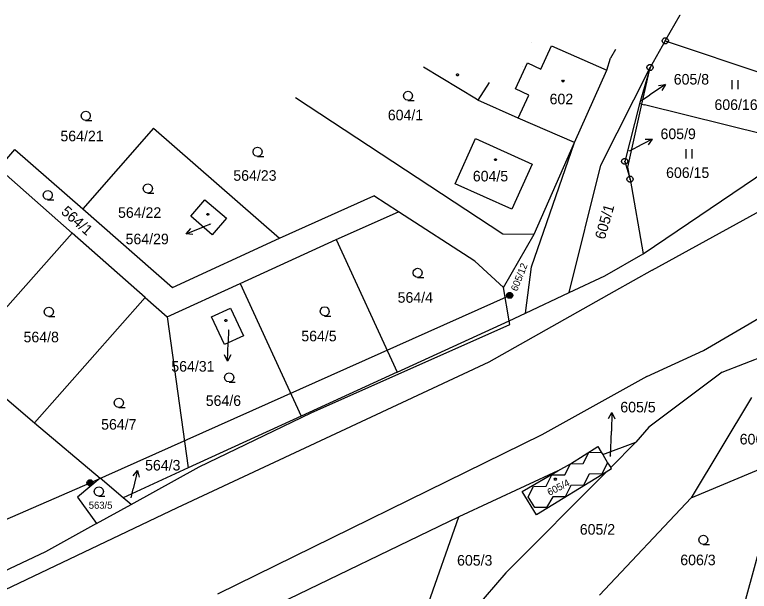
# Model space of a CAD drawing. Extents: x -759699 to -757730, y -1172308 to -1170857.
# Drawn here: x -759051 to -758932.7, y -1171592 to -1171499.1 of the extents above; entities that cross this region are included whole.
import ezdxf

# ---------------------------------------------------------------- set-up
doc = ezdxf.new("R2010")
doc.units = 0
for name, color, linetype in [('Vrstva 1', 7, 'Continuous'), ('Vrstva 12', 7, 'Continuous'), ('Vrstva 2', 7, 'Continuous'), ('Vrstva 3', 7, 'Continuous'), ('Vrstva 4', 7, 'Continuous'), ('Vrstva 5', 7, 'Continuous'), ('Vrstva 6', 7, 'Continuous'), ('Vrstva 7', 7, 'Continuous'), ('Vrstva 8', 7, 'Continuous')]:
    doc.layers.add(name, color=color, linetype=linetype)

msp = doc.modelspace()

# ---------------------------------------------------------------- linework, layer by layer
at = {"layer": 'Vrstva 1'}
for p, q in [((-758946.27, -1171503.31), (-758943.88, -1171499.09)), ((-758943.88, -1171499.09), (-758943.88, -1171499.09)), ((-758946.27, -1171503.31), (-758948.7, -1171507.6)), ((-758946.27, -1171503.31), (-758914.82, -1171513.88)), ((-758967.79, -1171503.49), (-758967.79, -1171503.49)), ((-758967.79, -1171503.49), (-758967.79, -1171503.49)), ((-758954.28, -1171504.71), (-758955.09, -1171506.07)), ((-758954.28, -1171504.71), (-758954.28, -1171504.71)), ((-758954.28, -1171504.71), (-758954.28, -1171504.71)), ((-758955.66, -1171508.01), (-758955.09, -1171506.07)), ((-758955.09, -1171506.07), (-758955.09, -1171506.07)), ((-758976.64, -1171512.71), (-758985.21, -1171507.56)), ((-758985.21, -1171507.56), (-758985.21, -1171507.56)), ((-758969.29, -1171507.45), (-758969.29, -1171507.45)), ((-758969.29, -1171507.45), (-758969.29, -1171507.45)), ((-758960.9, -1171519.69), (-758955.66, -1171508.01)), ((-758956.62, -1171523.33), (-758948.7, -1171507.6)), ((-758948.7, -1171507.6), (-758950.4, -1171513.43)), ((-758950.02, -1171513.52), (-758948.7, -1171507.6)), ((-759005.8, -1171512.44), (-759005.8, -1171512.44)), ((-759005.8, -1171512.44), (-759005.8, -1171512.44)), ((-759005.8, -1171512.44), (-758972.4, -1171534.4)), ((-758976.44, -1171512.83), (-758976.64, -1171512.71)), ((-758969.95, -1171515.76), (-758976.44, -1171512.83)), ((-758950.4, -1171513.43), (-758952.79, -1171522.73)), ((-758952.28, -1171523.63), (-758950.02, -1171513.52)), ((-758950.02, -1171513.52), (-758950.4, -1171513.43)), ((-758950.02, -1171513.52), (-758949.6, -1171513.62)), ((-758923.84, -1171519.99), (-758949.6, -1171513.62)), ((-758960.9, -1171519.69), (-758969.95, -1171515.76)), ((-759028.64, -1171517.34), (-759040.04, -1171530.35)), ((-759028.64, -1171517.34), (-759028.64, -1171517.34)), ((-759028.64, -1171517.34), (-759008.36, -1171535.09)), ((-758980.08, -1171526.33), (-758976.79, -1171519.04)), ((-758976.79, -1171519.04), (-758967.68, -1171523.15)), ((-758967.79, -1171539.68), (-758960.9, -1171519.69)), ((-758967.38, -1171534.45), (-758960.9, -1171519.69)), ((-759052.28, -1171522.29), (-759050.96, -1171520.79)), ((-759050.96, -1171520.79), (-759050.96, -1171520.79)), ((-759050.96, -1171520.79), (-759040.04, -1171530.35)), ((-758949.81, -1171537.59), (-758925.08, -1171520.83)), ((-758967.68, -1171523.15), (-758970.97, -1171530.42)), ((-758961.73, -1171543.84), (-758956.62, -1171523.33)), ((-758952.79, -1171522.73), (-758951.93, -1171525.59)), ((-759041.76, -1171534.25), (-759052.86, -1171524.45)), ((-758951.93, -1171525.59), (-758952.28, -1171523.63)), ((-758951.93, -1171525.59), (-758949.81, -1171537.59)), ((-758970.97, -1171530.42), (-758980.08, -1171526.33)), ((-759022.64, -1171531.54), (-759020.38, -1171528.89)), ((-759020.38, -1171528.89), (-759016.91, -1171531.88)), ((-759008.36, -1171535.09), (-758993.17, -1171528.25)), ((-758993.17, -1171528.25), (-758993.17, -1171528.25)), ((-758989.2, -1171530.82), (-758993.17, -1171528.25)), ((-759040.04, -1171530.35), (-759025.59, -1171543)), ((-759019.22, -1171534.55), (-759022.64, -1171531.54)), ((-758999.24, -1171535.3), (-758989.2, -1171530.82)), ((-758976.9, -1171538.8), (-758989.2, -1171530.82)), ((-759016.91, -1171531.88), (-759019.22, -1171534.55)), ((-759059.77, -1171554.66), (-759041.76, -1171534.25)), ((-759029.99, -1171544.64), (-759041.76, -1171534.25)), ((-759025.59, -1171543), (-759008.36, -1171535.09)), ((-759014.69, -1171542.38), (-758999.24, -1171535.3)), ((-758999.24, -1171535.3), (-758989.44, -1171556.65)), ((-758972.4, -1171534.4), (-758967.38, -1171534.45)), ((-758972.3, -1171543), (-758967.38, -1171534.45)), ((-758955.97, -1171541.14), (-758949.81, -1171537.59)), ((-758972.3, -1171543), (-758976.9, -1171538.8)), ((-758968.78, -1171547.15), (-758967.79, -1171539.68)), ((-758961.73, -1171543.84), (-758955.97, -1171541.14)), ((-759026.44, -1171547.77), (-759014.69, -1171542.38)), ((-759014.69, -1171542.38), (-759004.89, -1171563.74)), ((-758971.4, -1171548.38), (-758972.3, -1171543)), ((-759047.8, -1171564.8), (-759029.99, -1171544.64)), ((-759029.99, -1171544.64), (-759026.44, -1171547.77)), ((-758968.78, -1171547.15), (-758961.73, -1171543.84)), ((-759019.34, -1171547.74), (-759016.26, -1171546.38)), ((-759016.26, -1171546.38), (-759014.14, -1171550.81)), ((-759026.44, -1171547.77), (-759023.07, -1171572.08)), ((-759017.21, -1171552.22), (-759019.34, -1171547.74)), ((-758971.4, -1171548.38), (-758968.78, -1171547.15)), ((-759003.26, -1171563.2), (-758971.3, -1171549)), ((-758989.44, -1171556.65), (-758971.4, -1171548.38)), ((-758971.3, -1171549), (-758971.4, -1171548.38)), ((-758937.1, -1171556.66), (-758918.53, -1171549.43)), ((-759014.14, -1171550.81), (-759017.21, -1171552.22)), ((-759059.77, -1171554.66), (-759047.8, -1171564.8)), ((-758989.44, -1171556.65), (-759004.89, -1171563.74)), ((-758937.1, -1171556.66), (-758948.93, -1171565.54)), ((-758932.37, -1171560.76), (-758942.1, -1171576.91)), ((-759021.28, -1171571.93), (-759003.26, -1171563.2)), ((-759047.8, -1171564.8), (-759037.25, -1171573.72)), ((-759004.89, -1171563.74), (-759023.07, -1171572.08)), ((-758948.93, -1171565.54), (-758950.99, -1171567.95)), ((-758956.34, -1171569.92), (-758950.99, -1171567.95)), ((-758950.99, -1171567.95), (-758955.05, -1171572.03)), ((-758961.54, -1171571.4), (-758957.13, -1171568.64)), ((-758957.13, -1171568.64), (-758956.6, -1171569.57)), ((-758956.6, -1171569.57), (-758956.34, -1171569.92)), ((-758956.34, -1171569.92), (-758955.56, -1171571.28)), ((-758942.1, -1171576.91), (-758927.21, -1171570.62)), ((-758927.21, -1171570.62), (-758933.5, -1171593.84)), ((-759032.25, -1171578), (-759021.28, -1171571.93)), ((-758963.54, -1171572.57), (-758961.54, -1171571.4)), ((-758955.56, -1171571.28), (-758955.05, -1171572.03)), ((-759023.07, -1171572.08), (-759033.52, -1171576.88)), ((-758963.54, -1171572.57), (-758979.51, -1171579.97)), ((-758971.93, -1171588.99), (-758955.78, -1171572.76)), ((-758969.29, -1171575.88), (-758963.54, -1171572.57)), ((-758955.78, -1171572.76), (-758966.97, -1171579.63)), ((-758954.92, -1171572.23), (-758955.78, -1171572.76)), ((-758954.92, -1171572.23), (-758955.05, -1171572.03)), ((-759037.25, -1171573.72), (-759040.91, -1171576.77)), ((-759033.52, -1171576.88), (-759037.25, -1171573.72)), ((-758966.97, -1171579.63), (-758969.29, -1171575.88)), ((-759040.91, -1171576.77), (-759037.82, -1171581.06)), ((-759032.25, -1171578), (-759033.52, -1171576.88)), ((-758956.83, -1171592.6), (-758942.1, -1171576.91)), ((-759037.82, -1171581.06), (-759032.25, -1171578)), ((-758979.51, -1171579.97), (-759011.7, -1171595.5)), ((-758985.06, -1171595.81), (-758979.51, -1171579.97)), ((-759037.82, -1171581.06), (-759046.04, -1171585.58)), ((-759046.04, -1171585.58), (-759059.5, -1171591.95)), ((-758971.93, -1171588.99), (-758979.59, -1171597.85))]:
    msp.add_line(p, q, dxfattribs=at)
at = {"layer": 'Vrstva 12'}
for p, q in [((-758967.79, -1171503.49), (-758967.79, -1171503.49)), ((-758967.79, -1171503.49), (-758967.79, -1171503.49)), ((-758966.3, -1171507.85), (-758964.58, -1171504.08)), ((-758964.58, -1171504.08), (-758955.66, -1171508.01)), ((-758970.39, -1171511.05), (-758968.46, -1171506.86)), ((-758968.46, -1171506.86), (-758966.3, -1171507.85)), ((-758960.9, -1171519.69), (-758955.66, -1171508.01)), ((-758968.23, -1171512.04), (-758970.39, -1171511.05)), ((-758969.95, -1171515.76), (-758968.23, -1171512.04)), ((-758960.9, -1171519.69), (-758969.95, -1171515.76)), ((-758980.08, -1171526.33), (-758976.79, -1171519.04)), ((-758976.79, -1171519.04), (-758967.68, -1171523.15)), ((-758967.68, -1171523.15), (-758970.97, -1171530.42)), ((-758970.97, -1171530.42), (-758980.08, -1171526.33)), ((-759022.64, -1171531.54), (-759020.38, -1171528.89)), ((-759020.38, -1171528.89), (-759016.91, -1171531.88)), ((-759019.22, -1171534.55), (-759022.64, -1171531.54)), ((-759016.91, -1171531.88), (-759019.22, -1171534.55)), ((-759019.34, -1171547.74), (-759016.26, -1171546.38)), ((-759016.26, -1171546.38), (-759014.14, -1171550.81)), ((-759017.21, -1171552.22), (-759019.34, -1171547.74)), ((-759014.14, -1171550.81), (-759017.21, -1171552.22)), ((-758959.48, -1171571.37), (-758958.55, -1171569.6)), ((-758958.55, -1171569.6), (-758956.6, -1171569.57)), ((-758956.6, -1171569.57), (-758956.34, -1171569.92)), ((-758956.34, -1171569.92), (-758955.56, -1171571.28)), ((-758962.44, -1171573.17), (-758961.54, -1171571.4)), ((-758961.54, -1171571.4), (-758959.48, -1171571.37)), ((-758955.56, -1171571.28), (-758956.49, -1171573.05)), ((-758958.5, -1171573.08), (-758959.43, -1171574.85)), ((-758956.49, -1171573.05), (-758958.5, -1171573.08)), ((-758965.46, -1171575.01), (-758964.51, -1171573.22)), ((-758964.51, -1171573.22), (-758962.44, -1171573.17)), ((-758968.33, -1171576.75), (-758967.46, -1171575.07)), ((-758967.46, -1171575.07), (-758965.46, -1171575.01)), ((-758961.46, -1171574.91), (-758962.39, -1171576.72)), ((-758959.43, -1171574.85), (-758961.46, -1171574.91)), ((-758967.26, -1171578.47), (-758968.33, -1171576.75)), ((-758964.38, -1171576.73), (-758965.36, -1171578.48)), ((-758962.39, -1171576.72), (-758964.38, -1171576.73)), ((-758965.36, -1171578.48), (-758967.26, -1171578.47))]:
    msp.add_line(p, q, dxfattribs=at)
at = {"layer": 'Vrstva 3'}
for p, q in [((-758935.54, -1171509.61), (-758935.54, -1171511.11)), ((-758934.54, -1171511.11), (-758934.54, -1171509.61)), ((-758942.95, -1171520.75), (-758942.95, -1171522.25)), ((-758941.95, -1171522.25), (-758941.95, -1171520.75))]:
    msp.add_line(p, q, dxfattribs=at)
for points in [[(-758987.67, -1171512.88), (-758988.05, -1171512.78), (-758988.32, -1171512.51), (-758988.42, -1171512.14), (-758988.32, -1171511.77), (-758988.05, -1171511.5), (-758987.68, -1171511.4), (-758987.31, -1171511.5), (-758987.04, -1171511.77), (-758986.94, -1171512.15), (-758987.04, -1171512.53), (-758987.31, -1171512.8), (-758987.69, -1171512.9), (-758986.69, -1171512.9)], [(-759039.55, -1171516.12), (-759039.93, -1171516.02), (-759040.2, -1171515.75), (-759040.3, -1171515.38), (-759040.2, -1171515.01), (-759039.93, -1171514.74), (-759039.56, -1171514.64), (-759039.19, -1171514.74), (-759038.92, -1171515.01), (-759038.82, -1171515.39), (-759038.92, -1171515.77), (-759039.19, -1171516.04), (-759039.57, -1171516.14), (-759038.57, -1171516.14)], [(-759011.88, -1171521.92), (-759012.26, -1171521.82), (-759012.53, -1171521.55), (-759012.63, -1171521.18), (-759012.53, -1171520.81), (-759012.26, -1171520.54), (-759011.89, -1171520.44), (-759011.52, -1171520.54), (-759011.25, -1171520.81), (-759011.15, -1171521.19), (-759011.25, -1171521.57), (-759011.52, -1171521.84), (-759011.9, -1171521.94), (-759010.9, -1171521.94)], [(-759029.55, -1171527.81), (-759029.93, -1171527.71), (-759030.2, -1171527.44), (-759030.3, -1171527.07), (-759030.2, -1171526.7), (-759029.93, -1171526.43), (-759029.56, -1171526.33), (-759029.19, -1171526.43), (-759028.92, -1171526.7), (-759028.82, -1171527.08), (-759028.92, -1171527.46), (-759029.19, -1171527.73), (-759029.57, -1171527.83), (-759028.57, -1171527.83)], [(-759045.67, -1171528.88), (-759046.05, -1171528.78), (-759046.32, -1171528.51), (-759046.42, -1171528.14), (-759046.32, -1171527.77), (-759046.05, -1171527.5), (-759045.68, -1171527.4), (-759045.31, -1171527.5), (-759045.04, -1171527.77), (-759044.94, -1171528.15), (-759045.04, -1171528.53), (-759045.31, -1171528.8), (-759045.69, -1171528.9), (-759044.69, -1171528.9)], [(-758986.12, -1171541.39), (-758986.5, -1171541.29), (-758986.77, -1171541.02), (-758986.87, -1171540.65), (-758986.77, -1171540.28), (-758986.5, -1171540.01), (-758986.13, -1171539.91), (-758985.76, -1171540.01), (-758985.49, -1171540.28), (-758985.39, -1171540.66), (-758985.49, -1171541.04), (-758985.76, -1171541.31), (-758986.14, -1171541.41), (-758985.14, -1171541.41)], [(-759045.5, -1171547.69), (-759045.88, -1171547.59), (-759046.15, -1171547.32), (-759046.25, -1171546.95), (-759046.15, -1171546.58), (-759045.88, -1171546.31), (-759045.51, -1171546.21), (-759045.14, -1171546.31), (-759044.87, -1171546.58), (-759044.77, -1171546.96), (-759044.87, -1171547.34), (-759045.14, -1171547.61), (-759045.52, -1171547.71), (-759044.52, -1171547.71)], [(-759001.09, -1171547.6), (-759001.47, -1171547.5), (-759001.74, -1171547.23), (-759001.84, -1171546.86), (-759001.74, -1171546.49), (-759001.47, -1171546.22), (-759001.1, -1171546.12), (-759000.73, -1171546.22), (-759000.46, -1171546.49), (-759000.36, -1171546.87), (-759000.46, -1171547.25), (-759000.73, -1171547.52), (-759001.11, -1171547.62), (-759000.11, -1171547.62)], [(-759016.46, -1171558.24), (-759016.84, -1171558.14), (-759017.11, -1171557.87), (-759017.21, -1171557.5), (-759017.11, -1171557.13), (-759016.84, -1171556.86), (-759016.47, -1171556.76), (-759016.1, -1171556.86), (-759015.83, -1171557.13), (-759015.73, -1171557.51), (-759015.83, -1171557.89), (-759016.1, -1171558.16), (-759016.48, -1171558.26), (-759015.48, -1171558.26)], [(-759034.21, -1171562.33), (-759034.59, -1171562.23), (-759034.86, -1171561.96), (-759034.96, -1171561.59), (-759034.86, -1171561.22), (-759034.59, -1171560.95), (-759034.22, -1171560.85), (-759033.85, -1171560.95), (-759033.58, -1171561.22), (-759033.48, -1171561.6), (-759033.58, -1171561.98), (-759033.85, -1171562.25), (-759034.23, -1171562.35), (-759033.23, -1171562.35)], [(-759037.45, -1171576.61), (-759037.83, -1171576.51), (-759038.1, -1171576.24), (-759038.2, -1171575.87), (-759038.1, -1171575.5), (-759037.83, -1171575.23), (-759037.46, -1171575.13), (-759037.09, -1171575.23), (-759036.82, -1171575.5), (-759036.72, -1171575.88), (-759036.82, -1171576.26), (-759037.09, -1171576.53), (-759037.47, -1171576.63), (-759036.47, -1171576.63)], [(-758940.13, -1171584.39), (-758940.51, -1171584.29), (-758940.78, -1171584.02), (-758940.88, -1171583.65), (-758940.78, -1171583.28), (-758940.51, -1171583.01), (-758940.14, -1171582.91), (-758939.77, -1171583.01), (-758939.5, -1171583.28), (-758939.4, -1171583.66), (-758939.5, -1171584.04), (-758939.77, -1171584.31), (-758940.15, -1171584.41), (-758939.15, -1171584.41)]]:
    msp.add_lwpolyline(points, dxfattribs=at)
at = {"layer": 'Vrstva 4'}
for p, q in [((-758966.3, -1171507.85), (-758964.58, -1171504.08)), ((-758964.58, -1171504.08), (-758955.66, -1171508.01)), ((-758970.39, -1171511.05), (-758968.46, -1171506.86)), ((-758968.46, -1171506.86), (-758966.3, -1171507.85)), ((-758985.21, -1171507.56), (-758985.21, -1171507.56)), ((-758974.59, -1171510), (-758976.44, -1171512.83)), ((-758974.59, -1171510), (-758974.59, -1171510)), ((-758968.23, -1171512.04), (-758970.39, -1171511.05)), ((-758969.95, -1171515.76), (-758968.23, -1171512.04)), ((-758948.39, -1171540.22), (-758926.31, -1171528.12)), ((-758940.14, -1171553.19), (-758911.34, -1171536.26)), ((-758948.39, -1171540.22), (-758954.49, -1171543.68)), ((-758954.49, -1171543.68), (-758974.67, -1171555.07)), ((-758949.21, -1171557.34), (-758940.14, -1171553.19)), ((-758974.67, -1171555.07), (-759024.83, -1171578.53)), ((-758949.21, -1171557.34), (-758966.16, -1171566.77)), ((-758966.16, -1171566.77), (-759018.34, -1171592.41)), ((-758959.48, -1171571.37), (-758958.55, -1171569.6)), ((-758958.55, -1171569.6), (-758956.6, -1171569.57)), ((-758962.44, -1171573.17), (-758961.54, -1171571.4)), ((-758961.54, -1171571.4), (-758959.48, -1171571.37)), ((-758955.56, -1171571.28), (-758956.49, -1171573.05)), ((-758958.5, -1171573.08), (-758959.43, -1171574.85)), ((-758956.49, -1171573.05), (-758958.5, -1171573.08)), ((-758965.46, -1171575.01), (-758964.51, -1171573.22)), ((-758964.51, -1171573.22), (-758962.44, -1171573.17)), ((-758968.33, -1171576.75), (-758967.46, -1171575.07)), ((-758967.46, -1171575.07), (-758965.46, -1171575.01)), ((-758961.46, -1171574.91), (-758962.39, -1171576.72)), ((-758959.43, -1171574.85), (-758961.46, -1171574.91)), ((-758967.26, -1171578.47), (-758968.33, -1171576.75)), ((-758964.38, -1171576.73), (-758965.36, -1171578.48)), ((-758962.39, -1171576.72), (-758964.38, -1171576.73)), ((-759024.83, -1171578.53), (-759072.45, -1171601.16)), ((-758965.36, -1171578.48), (-758967.26, -1171578.47))]:
    msp.add_line(p, q, dxfattribs=at)
at = {"layer": 'Vrstva 5'}
for points in [[(-758979.62, -1171508.62), (-758979.53, -1171508.77), (-758979.62, -1171508.92), (-758979.8, -1171508.92), (-758979.89, -1171508.77), (-758979.8, -1171508.62)], [(-758962.64, -1171509.63), (-758962.55, -1171509.78), (-758962.64, -1171509.93), (-758962.82, -1171509.93), (-758962.91, -1171509.78), (-758962.82, -1171509.63)], [(-758973.51, -1171522.28), (-758973.42, -1171522.43), (-758973.51, -1171522.58), (-758973.69, -1171522.58), (-758973.78, -1171522.43), (-758973.69, -1171522.28)], [(-759019.81, -1171531.1), (-759019.72, -1171531.25), (-759019.81, -1171531.4), (-759019.99, -1171531.4), (-759020.08, -1171531.25), (-759019.99, -1171531.1)], [(-759016.91, -1171548.19), (-759016.82, -1171548.34), (-759016.91, -1171548.49), (-759017.09, -1171548.49), (-759017.18, -1171548.34), (-759017.09, -1171548.19)], [(-758963.86, -1171573.75), (-758963.77, -1171573.9), (-758963.86, -1171574.05), (-758964.04, -1171574.05), (-758964.13, -1171573.9), (-758964.04, -1171573.75)]]:
    msp.add_lwpolyline(points, close=True, dxfattribs=at)
at = {"layer": 'Vrstva 6'}
for p, q in [((-759038.87, -1171574.49), (-758971.32, -1171544.31)), ((-759105.39, -1171603.36), (-759038.87, -1171574.49))]:
    msp.add_line(p, q, dxfattribs=at)
for points in [[(-758971.47, -1171543.83), (-758971.16, -1171543.83), (-758970.91, -1171544.01), (-758970.81, -1171544.3), (-758970.91, -1171544.59), (-758971.16, -1171544.77), (-758971.47, -1171544.77), (-758971.72, -1171544.59), (-758971.82, -1171544.3), (-758971.72, -1171544.01), (-758971.47, -1171543.83), (-758971.44, -1171543.87), (-758971.2, -1171543.87), (-758971.04, -1171543.95), (-758971.6, -1171543.95), (-758971.68, -1171544.03), (-758970.96, -1171544.03), (-758970.96, -1171544.11), (-758971.68, -1171544.11), (-758971.72, -1171544.19), (-758970.92, -1171544.19), (-758970.88, -1171544.27), (-758971.76, -1171544.27), (-758971.76, -1171544.35), (-758970.88, -1171544.35), (-758970.91, -1171544.43), (-758971.72, -1171544.43), (-758971.71, -1171544.51), (-758970.9, -1171544.51), (-758970.95, -1171544.59), (-758971.67, -1171544.59), (-758971.59, -1171544.67), (-758971.03, -1171544.67), (-758971.14, -1171544.75), (-758971.48, -1171544.75)], [(-759039.02, -1171574.01), (-759038.71, -1171574.01), (-759038.46, -1171574.19), (-759038.36, -1171574.48), (-759038.46, -1171574.77), (-759038.71, -1171574.95), (-759039.02, -1171574.95), (-759039.27, -1171574.77), (-759039.37, -1171574.48), (-759039.27, -1171574.19), (-759039.02, -1171574.01), (-759038.99, -1171574.05), (-759038.75, -1171574.05), (-759038.59, -1171574.13), (-759039.15, -1171574.13), (-759039.23, -1171574.21), (-759038.51, -1171574.21), (-759038.51, -1171574.29), (-759039.23, -1171574.29), (-759039.27, -1171574.37), (-759038.47, -1171574.37), (-759038.43, -1171574.45), (-759039.31, -1171574.45), (-759039.31, -1171574.53), (-759038.43, -1171574.53), (-759038.46, -1171574.61), (-759039.27, -1171574.61), (-759039.26, -1171574.69), (-759038.45, -1171574.69), (-759038.5, -1171574.77), (-759039.22, -1171574.77), (-759039.14, -1171574.85), (-759038.58, -1171574.85), (-759038.69, -1171574.93), (-759039.03, -1171574.93)]]:
    msp.add_lwpolyline(points, dxfattribs=at)
at = {"layer": 'Vrstva 7'}
for p, q in [((-758946.257, -1171510.337), (-758948.74, -1171512.02)), ((-758950.07, -1171512.92), (-758948.74, -1171512.02)), ((-758948.388, -1171519.136), (-758951.05, -1171520.52)), ((-758952.02, -1171521.02), (-758951.05, -1171520.52)), ((-759019.47, -1171532.83), (-759020.62, -1171533.28)), ((-759023.418, -1171534.363), (-759020.62, -1171533.28)), ((-759016.56, -1171549.86), (-759016.63, -1171551.87)), ((-759016.731, -1171554.868), (-759016.63, -1171551.87)), ((-758954.862, -1171563.141), (-758954.95, -1171566.14)), ((-758955.07, -1171570.23), (-758954.95, -1171566.14)), ((-759031.239, -1171572.504), (-759031.9, -1171575.43)), ((-759032.23, -1171576.88), (-759031.9, -1171575.43))]:
    msp.add_line(p, q, dxfattribs=at)
for points in [[(-758947.365, -1171510.484), (-758946.257, -1171510.337), (-758946.804, -1171511.312)], [(-758949.506, -1171519.154), (-758948.388, -1171519.136), (-758949.045, -1171520.041)], [(-759022.305, -1171534.468), (-759023.418, -1171534.363), (-759022.666, -1171533.535)], [(-759016.197, -1171553.886), (-759016.731, -1171554.868), (-759017.197, -1171553.852)], [(-758955.391, -1171564.126), (-758954.862, -1171563.141), (-758954.392, -1171564.155)], [(-759031.947, -1171573.369), (-759031.239, -1171572.504), (-759030.972, -1171573.589)]]:
    msp.add_lwpolyline(points, dxfattribs=at)
at = {"layer": 'Vrstva 8'}
for p, q in [((-758946.39, -1171503.31), (-758946.15, -1171503.31)), ((-758948.82, -1171507.6), (-758948.58, -1171507.6)), ((-758952.91, -1171522.73), (-758952.67, -1171522.73)), ((-758952.05, -1171525.59), (-758951.81, -1171525.59))]:
    msp.add_line(p, q, dxfattribs=at)
for points in [[(-758946.12, -1171502.83), (-758945.87, -1171503.01), (-758945.77, -1171503.3), (-758945.87, -1171503.59), (-758946.12, -1171503.77), (-758946.43, -1171503.77), (-758946.68, -1171503.59), (-758946.78, -1171503.3), (-758946.68, -1171503.01), (-758946.43, -1171502.83)], [(-758948.55, -1171507.12), (-758948.3, -1171507.3), (-758948.2, -1171507.59), (-758948.3, -1171507.88), (-758948.55, -1171508.06), (-758948.86, -1171508.06), (-758949.11, -1171507.88), (-758949.21, -1171507.59), (-758949.11, -1171507.3), (-758948.86, -1171507.12)], [(-758952.64, -1171522.25), (-758952.39, -1171522.43), (-758952.29, -1171522.72), (-758952.39, -1171523.01), (-758952.64, -1171523.19), (-758952.95, -1171523.19), (-758953.2, -1171523.01), (-758953.3, -1171522.72), (-758953.2, -1171522.43), (-758952.95, -1171522.25)], [(-758951.78, -1171525.11), (-758951.53, -1171525.29), (-758951.43, -1171525.58), (-758951.53, -1171525.87), (-758951.78, -1171526.05), (-758952.09, -1171526.05), (-758952.34, -1171525.87), (-758952.44, -1171525.58), (-758952.34, -1171525.29), (-758952.09, -1171525.11)]]:
    msp.add_lwpolyline(points, close=True, dxfattribs=at)

# ---------------------------------------------------------------- texts
at = {"layer": 'Vrstva 2'}
for s, height, p in [('602', 1.7, (-758964.885, -1171513.52)), ('606/16', 1.7, (-758938.351, -1171514.43)), ('604/1', 1.7, (-758990.932, -1171516.1)), ('564/21', 1.7, (-759043.635, -1171519.48)), ('605/9', 0.1, (-758952.226, -1171521.02)), ('564/23', 1.7, (-759015.8, -1171525.84)), ('604/5', 1.7, (-758977.247, -1171525.94)), ('606/15', 1.7, (-758946.138, -1171525.38)), ('564/22', 1.7, (-759034.357, -1171531.81)), ('564/29', 0.1, (-759019.72, -1171532.83)), ('564/4', 1.7, (-758989.35, -1171545.48)), ('564/8', 1.7, (-759049.57, -1171551.85)), ('564/31', 0.1, (-759016.79, -1171549.86)), ('564/5', 1.7, (-759004.857, -1171551.69)), ('564/6', 1.7, (-759020.24, -1171562.1)), ('564/7', 1.7, (-759037.08, -1171565.92)), ('606/2', 1.7, (-758934.284, -1171568.3)), ('605/5', 0.1, (-758955.279, -1171570.23)), ('563/5', 1.14, (-759039.073, -1171578.66)), ('564/3', 0.1, (-759032.44, -1171576.88)), ('605/2', 1.7, (-758960.03, -1171582.83)), ('605/3', 1.7, (-758979.784, -1171587.81)), ('606/3', 1.7, (-758943.847, -1171587.75))]:
    msp.add_text(s, height=height, dxfattribs=at).set_placement(p)
for s, height, rotation, p in [('605/8', 0.1, 75.00018, (-758950.124, -1171513.12)), ('564/1', 1.7, 318.62183, (-759043.65, -1171531.01)), ('605/1', 1.7, 74.14074, (-758956.003, -1171535.399)), ('605/12', 1.14, 68.41116, (-758970.118, -1171543.725)), ('605/4', 1.14, 27.50198, (-758964.896, -1171576.606))]:
    msp.add_text(s, height=height, rotation=rotation, dxfattribs=at).set_placement(p)
at = {"layer": 'Vrstva 7'}
for s, p in [('605/8', (-758944.903, -1171510.34)), ('605/9', (-758947.033, -1171519.13)), ('564/29', (-759033.144, -1171536.06)), ('564/31', (-759025.785, -1171556.57)), ('605/5', (-758953.503, -1171563.14)), ('564/3', (-759030.003, -1171572.5))]:
    msp.add_text(s, height=1.7, dxfattribs=at).set_placement(p)

doc.saveas('drawing.dxf')
